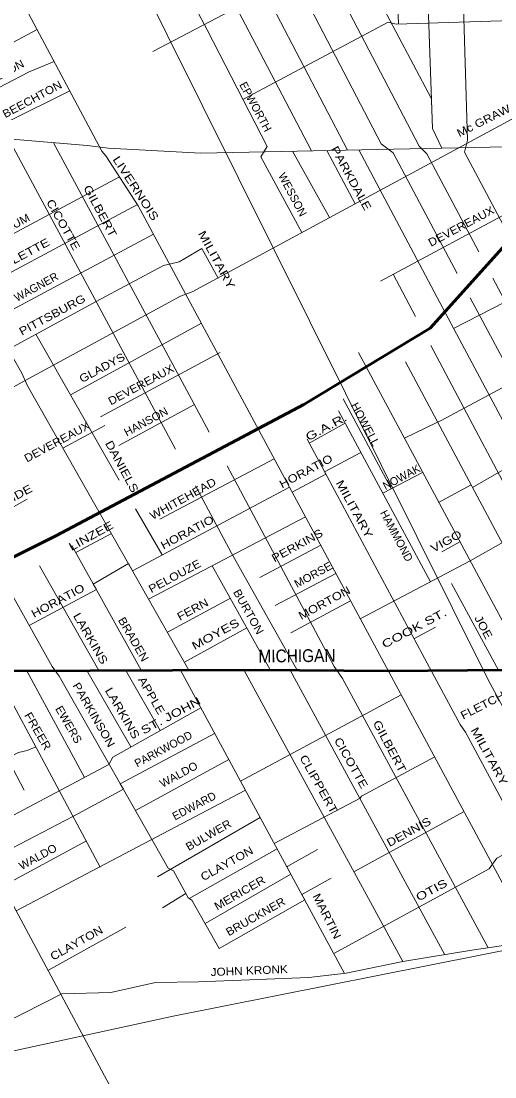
# Model space of a CAD drawing. Extents: x 34705 to 138605, y 34275 to 143551.
# Drawn here: x 76640 to 81081, y 96052 to 105948 of the extents above; entities that cross this region are included whole.
import ezdxf
from ezdxf.enums import TextEntityAlignment as Align

# ---------------------------------------------------------------- set-up
doc = ezdxf.new("R2010")
doc.units = 0
doc.header["$LTSCALE"] = 30
for name, color, linetype, lineweight in [('1', 7, 'Continuous', 13), ('11', 7, 'Continuous', 13), ('50', 7, 'Continuous', 13), ('51', 7, 'Continuous', 35)]:
    doc.layers.add(name, color=color, linetype=linetype, lineweight=lineweight)

msp = doc.modelspace()

# ---------------------------------------------------------------- linework, layer by layer
at = {"layer": '1'}
for p, q in [((79336.97, 107393.55), (80482.05, 105225.38)), ((76526.27, 104843.04), (78087.16, 101937.59)), ((79182.23, 104729.2), (79529.11, 104106.04)), ((79505.13, 104735.87), (79771.58, 104236.98)), ((76068.54, 103690.72), (77561.14, 104489.35)), ((76211.58, 103415.72), (77731.03, 104228.71)), ((80126.03, 103575.2), (80335.18, 103180.12)), ((81060.36, 103538.87), (83000.02, 99882.54)), ((80850.45, 103354.36), (82698.38, 99879.92)), ((77109.3, 102447.52), (78330.31, 103116.38)), ((76777.04, 103013.06), (77559.48, 101646.02)), ((77382.57, 102238.13), (78504.74, 102843.02)), ((79800.98, 102840.94), (81370.26, 99915.88)), ((77557, 101970.59), (78266.35, 102354.46)), ((79657.99, 102407.96), (80109.94, 101566.72)), ((79616, 102294.02), (80476.35, 100692.63)), ((77031.99, 101946.93), (77423.27, 102158.17)), ((79338.89, 101993.48), (79676.91, 102180.66)), ((77940.75, 101278.46), (79012.51, 101846.74)), ((80029.14, 101525.04), (80403.39, 101718.08)), ((76209.21, 101195.25), (76696.87, 101466.26)), ((77712.83, 101378.09), (77961.17, 100944.21)), ((77835.32, 100530.82), (79306.03, 101301.16)), ((77152.35, 100968.38), (77487.23, 101144.69)), ((78876.85, 100731.74), (79448.84, 101035.71)), ((80583.35, 100974.56), (80751.97, 101067.62)), ((77116.03, 101033.96), (77764.07, 99863.42)), ((76812.74, 100843.05), (77369.48, 99861.44)), ((78431.72, 100843.21), (78975.04, 99867.47)), ((79022.21, 100470.01), (79590.66, 100772.1)), ((80674.92, 100677.06), (81112.95, 99866.12)), ((78011.62, 100220.05), (78601.54, 100538.25)), ((79167.57, 100214.1), (79728.73, 100515.46)), ((78171.38, 99938.43), (78755.54, 100261.68)), ((80321.8, 100159.5), (80523.75, 100266.45)), ((76071.35, 99854.81), (76669.03, 98740.45)), ((76396.59, 99856.53), (77379.96, 98019.42)), ((76694.56, 99858.06), (77233.73, 98858.95)), ((77256.9, 99860.87), (77668.04, 99145.08)), ((77621.85, 99862.7), (77942.25, 99297.68)), ((78132.62, 99865.26), (79672.4, 97020.45)), ((78726.52, 99868.24), (80217.17, 97133.68)), ((79160.73, 99865.74), (80611.16, 97197.59)), ((77711.03, 98550.74), (78586.45, 99026.8)), ((77917.19, 97927.07), (78881.18, 98482.27)), ((79759.46, 97973.34), (80791.89, 98539.31))]:
    msp.add_line(p, q, dxfattribs=at)
for points in [[(70250.71, 99424.31), (70850.19, 99436.19), (73834.03, 101054.55), (75208.58, 101797.66), (76359.25, 102405.35), (76679.04, 102579.83), (78132.62, 103370.83), (78243.09, 103411.55), (82564.58, 105745.28), (82901.81, 106065.17), (82895.99, 106059.36), (83186.71, 106338.54), (83994.9, 106937.6), (84082.11, 106978.32), (85329.53, 107917.67), (85364.44, 107987.53), (85905.64, 108383.37), (87249.9, 109402.07), (88876.39, 110091.88)], [(74914.4, 104874.31), (75879.58, 104897.58), (77259.02, 104781.25), (77456.7, 104757.99), (78323.04, 104711.46), (84801.63, 104845.23), (85092.35, 104868.5), (85377.25, 104932.47), (86652.03, 105479.2), (88419.59, 106217.85), (88564.94, 106305.1), (90681.35, 107194.97), (91332.56, 107474.15), (91408.14, 107549.76), (94615.68, 108918.91), (95226.7, 109227.44), (95367, 109272.3)], [(79859.14, 108820.93), (80363.34, 107847.51), (80396.14, 107775.33), (80494.54, 104940.6), (80582.81, 104758.12)], [(77358.07, 108575.44), (77940.09, 107470.6), (77986.16, 107360), (79362.95, 104732.93)], [(78018.92, 108640.3), (78644.99, 107452.17), (78695.67, 107332.34), (80015.68, 104799.53), (80127.19, 104714.23), (80728.47, 103583.71)], [(76970.6, 108537.4), (77000.23, 108482.2), (78382.38, 105865.65), (78946.44, 104773.28), (78887.41, 104674.86), (79272.02, 103967.21)], [(75461.99, 108389.33), (75949.8, 107475.21), (75982.05, 107419.91), (76018.91, 107313.91), (77396.45, 104728.46), (77433.31, 104686.98), (77737.38, 104216.9), (82924.91, 94574.55), (82977.39, 94535.18), (83082.34, 94397.38), (83174.18, 94325.2), (83252.9, 94239.89), (83370.97, 94092.26), (86141.27, 88934.48)], [(80617.6, 107976.22), (80684.77, 107834.38), (80697.89, 107368.49), (80770.05, 106613.88), (80802.85, 105557.42), (80822.52, 104832.34), (80796.29, 104720.79), (81159.02, 104037.5)], [(80065.18, 107695.98), (80114.07, 107598.16), (80175.74, 105920.44)], [(78998.92, 107532.54), (78998.92, 107427.55), (79025.16, 107355.37), (80369.9, 104776.56), (80442.06, 104704.38), (80929.37, 103785.78)], [(78307.64, 107421.61), (78589.7, 106866.87), (79699.68, 104739.88)], [(77875.34, 105663.86), (79724.29, 106635.16), (79776.62, 106646.79), (83722.42, 106735.63)], [(78719.21, 105213.34), (80078.96, 105937.22), (80154.55, 105919.77), (82817.89, 106003.49)], [(74897.81, 105042.82), (75285.06, 105060.43), (75947.89, 105421.03), (76789.15, 105868.28)], [(75914.7, 104894.62), (75843.24, 105019.72), (76715.38, 105473.38), (76949.06, 105568.14)], [(76478.69, 104847.06), (76506.07, 105002.27), (76506.07, 105002.27), (77095.16, 105293.93)], [(79819.31, 100347.1), (80849.35, 100888.78), (81157.51, 101063.26), (81390.09, 101179.59), (82385.53, 101727.1), (82404.38, 101691.59), (83852.83, 102468.28), (83914.13, 102353.8), (84532.72, 102680.17), (84619.93, 102761.59), (84869.95, 102889.55), (85242.07, 103052.4), (85300.21, 103052.4), (86410.74, 103506.06), (87338.12, 103914.64), (90408.69, 105206.69)], [(75375.48, 104885.43), (76647.46, 102649.52), (76701.26, 102529.92), (78212.65, 99865.66)], [(76943.88, 104807.83), (78258.96, 102365.42), (78403.08, 102095.22)], [(79805.86, 104742.08), (80593.07, 103258.6), (80744.67, 102970.46), (82397.49, 99877.3)], [(80693.61, 103067.51), (81174.96, 103314.13), (81791.27, 103639.84), (82163.39, 103843.4), (83252.36, 104429.51)], [(74488.02, 104311.75), (74944.76, 103434.72), (74944.76, 103434.72), (75692.26, 102103.72), (75746.06, 102031.92), (76499.46, 100670.92), (76930.06, 99899.22), (76995.76, 99809.52), (78019.76, 98007.42), (78067.66, 97983.52), (78205.16, 97732.22), (78241.06, 97708.32), (78496.67, 97256.25)], [(80006.99, 103511.34), (81323.96, 104217.9), (81421.52, 104314.94)], [(73058.51, 101374.39), (74455.07, 102126.17), (74495.77, 102149.43), (75135.35, 102498.41), (75199.3, 102515.85), (77208.14, 103593.31), (77879.86, 103952.05)], [(76182, 102689.76), (77341.87, 103319.95), (77975.63, 103657.29), (78120.99, 103692.18), (78335.3, 103817.24), (78487.26, 103539.66)], [(80233.04, 102040.38), (80535.38, 102185.79), (80576.08, 102203.24), (83233.6, 103624.89)], [(73374.93, 103580.67), (73766.86, 102827.52), (73832.56, 102809.62), (74574.06, 101445.62), (75417.16, 99887.32), (75423.16, 99791.62), (80033.46, 91181.82), (80063.36, 91104.02), (80087.26, 90918.52), (80105.16, 90810.92), (80827.3, 89465.66)], [(80552.82, 101435.5), (80856.97, 101602.43), (80870.05, 101577.95), (81343.57, 101848.45), (81361.01, 101865.9), (81581.96, 101988.04), (82111.06, 102273.03), (82157.57, 102302.11), (83018.09, 102767.41), (83070.42, 102685.98), (83585.74, 102967.16)], [(80478.99, 102908.46), (81488.33, 101001.86), (82072.15, 99915.88), (82065.59, 99804.33), (82555.16, 98882.12)], [(80241.21, 102755.03), (81186.58, 100985.47), (81790.29, 99872.02)], [(79319.72, 102029.25), (80445.33, 99929.01), (80753.64, 99354.85), (80806.12, 99282.67), (82682.2, 95785.2)], [(79180.73, 101534.06), (79496.02, 101700.3), (79483.57, 101723.53), (79825.65, 101903.8)], [(78571.76, 101779.01), (79574.46, 99899.22), (79652.26, 99785.62), (81016.16, 97261.28)], [(76716.6, 100281.77), (77344.93, 100620.51), (77316.69, 100671.51), (77645.52, 100865.39), (77684.19, 100797.23), (79156.76, 101578.61)], [(78273.13, 101591.43), (78611.76, 100961.12), (79228.25, 99865.11)], [(76592.7, 97607.49), (78741.86, 98740.85), (78696.68, 98823.14), (80201.27, 99632.68)], [(76212.6, 98317.34), (77463.29, 98980.71), (77498.2, 99050.56), (77498.2, 99050.56), (78324.54, 99510.43)], [(76338.12, 98082.92), (77131.59, 98497.55), (77598.24, 98749.23), (77569.43, 98799.93), (78452.57, 99271.76)], [(75004.55, 98225.68), (75963.36, 98743.49), (76027.37, 98790.06), (76615.12, 99092.76), (76696.59, 99110.23), (76776.6, 99146.6)], [(77963.75, 97636.01), (78184.7, 97769.8), (78205.16, 97732.22), (78214.92, 97725.72), (79040.3, 98189.03), (79011.85, 98240.85), (79817.2, 98666.36), (79828.83, 98683.83), (80516.54, 99051.11)], [(79570.25, 97209.17), (81027.61, 98002.75), (81097.44, 98101.71), (81685.03, 98412.88)], [(76467.36, 97841.56), (77253.79, 98264.7), (77253.79, 98264.7)], [(78364.87, 97489.36), (79168.12, 97952.7), (79131.2, 98020.33), (79139.24, 98026.03), (79418.57, 98183.21)], [(79546.6, 97915.43), (79270.57, 97762.85), (79298.93, 97710.46), (78496.67, 97256.25)], [(72840.79, 95705.51), (75339.24, 96190.9), (75740.78, 96260.76), (75996.82, 96348.08), (76287.79, 96458.68), (77021.02, 96831.23), (77480.75, 96842.88), (77899.73, 96936.01), (78301.27, 96941.84), (79337.1, 96982.58), (79686.26, 97023.33), (80218.73, 97133.93), (80864.67, 97238.72), (81138.18, 97279.46), (81475.69, 97374.06), (81801.14, 97427.72), (81747.3, 97528.08), (82063.69, 97698.28)], [(76891.36, 97049.75), (77620.41, 97455.56), (77620.41, 97455.56)]]:
    msp.add_lwpolyline(points, dxfattribs=at)
at = {"layer": '1', "lineweight": 53}
msp.add_lwpolyline([(70273.25, 98655.39), (71057.35, 98936.8), (71901.7, 99280.47), (72734.73, 99461.12), (73549.47, 99618.3), (74194.43, 99751.98), (74462.66, 99868.63), (74760.14, 99892.09), (75412.24, 99851.32), (76511.78, 99857.14), (78835.21, 99868.78), (80080.52, 99857.14), (86770.24, 99915.34), (86956.45, 99956.09), (88909.68, 99973.56), (89759.8, 99996.86), (90394.28, 99932.82), (90847.72, 99926.99), (94474.35, 99938.64), (95736.38, 99991), (96334.87, 100081.57)], dxfattribs=at)
at = {"layer": '50'}
for points in [[(81906.05, 98139.06), (81018.13, 99774.79), (76672.7, 108508.16)], [(72952.8, 95508.64), (78064.89, 96622.26), (81430.09, 97291.04), (86167.76, 98196.23), (89160.46, 98763.08), (89727.54, 98776.38), (90401.7, 98740.87), (90973.35, 98653.39), (91592.71, 98503.02), (92169.12, 98306.86)]]:
    msp.add_lwpolyline(points, dxfattribs=at)
at = {"layer": '51', "lineweight": 60}
msp.add_lwpolyline([(69855.84, 98897.31), (71068.51, 99251.13), (71798.78, 99505.57), (71908.53, 99566.11), (73894.22, 100075), (74115.76, 100095.52), (75030.66, 100259.68), (75589.64, 100438.2), (76964.04, 101123.57), (79290.25, 102354.77), (80472.84, 103069.89), (82167.24, 104949.52), (82488.27, 105229.61), (83616.5, 105873.94), (83928.31, 105972.43), (86533.5, 107068.2), (87067.87, 107328.8), (89988.97, 108477.92)], dxfattribs=at)

# ---------------------------------------------------------------- texts
at = {"layer": '11'}
for s, height, rotation, width, p in [('WALTON', 75, 28.253, 1.05, (76477.67, 105418.41)), ('BEECHTON', 75, 28.252, 1.1, (76761.09, 105182.31)), ('Mc GRAW', 75, 26.74, 1.15, (80990.94, 104981.01)), ('PARKDALE ', 75, 298.729, 1.25, (79709.19, 104442.4)), ('LIVERNOIS', 75, 302.897, 1.3, (77682.92, 104360.99)), ('GILBERT', 75, 298.252, 1.25, (77347.77, 104149.92)), ('CICOTTE', 75, 299.253, 1.2, (77002.25, 104022.12)), ('DEVEREAUX', 75, 27.998, 1.1, (80781.5, 103991.88)), ('BARLUM', 75, 28.253, 1.1, (76528.39, 103972.44)), ('WILLETTE', 75, 28.253, 1.25, (76645.66, 103707.22)), ('MILITARY', 75, 298.614, 1.3, (78439.01, 103693.66)), ('PITTSBURG', 75, 28.254, 1.2, (76949.83, 103162.21)), ('GLADYS', 75, 28.325, 1.15, (77416.03, 102666.14)), ('DEVEREAUX', 75, 28.327, 1.1, (77780.66, 102506.96)), ('HANSON', 75, 28.328, 1.05, (77827.49, 102160.74)), ('HOWELL', 75, 298.223, 1.05, (79833.57, 102151.87)), ('G.A.R.', 75, 28.221, 1.4, (79516.9, 102109.71)), ('DEVEREAUX', 75, 28.327, 1.1, (76993.87, 101971.45)), ('DANIELS', 75, 298.324, 1.25, (77551.7, 101755.43)), ('HORATIO', 75, 28.223, 1.2, (79327.11, 101696.14)), ('WHITEHEAD', 75, 28.846, 1.15, (78174.34, 101438.65)), ('MILITARY', 75, 298.614, 1.3, (79730.65, 101356.81)), ('IRONSIDE', 75, 28.329, 1.25, (76486.63, 101399.38)), ('LINZEE', 75, 28.847, 1.3, (77312.44, 101090.13)), ('HORATIO', 75, 28.223, 1.2, (78214.73, 101123.81)), ('PERKINS', 75, 28.693, 1.2, (79245.68, 101000.19)), ('VIGO', 75, 28.693, 1.25, (80641.63, 101039.98)), ('PELOUZE', 75, 28.327, 1.15, (78097.08, 100712.66)), ('MORSE', 75, 28.693, 1.05, (79395.45, 100726.47)), ('HORATIO', 75, 28.223, 1.2, (77002.17, 100482.16)), ('MORTON ', 75, 28.693, 1.2, (79514.77, 100470.08)), ('BURTON', 75, 299.355, 1.1, (78738.25, 100393.94)), ('FERN', 75, 28.333, 1.15, (78265.75, 100400.95)), ('LARKINS', 75, 300.069, 1.25, (77258.65, 100143.28)), ('BRADEN', 75, 300.069, 1.1, (77660.36, 100135.35)), ('COOK ST. ', 75, 28.034, 1.4, (80358.72, 100233.31)), ('JOE', 75, 298.223, 1.2, (80941.16, 100250.99)), ('MOYES  ', 75, 28.693, 1.35, (78512.55, 100187.12)), ('MICHIGAN', 120, 0.658, 0.9, (79226.25, 99939.54)), ('PARKINSON', 75, 300.069, 1.15, (77289.48, 99427.88)), ('APPLE', 75, 300.069, 1.2, (77829.4, 99608.52)), ('LARKINS', 75, 300.069, 1.25, (77557.07, 99443.1)), ('FLETCHER', 75, 27.195, 1.15, (81053.92, 99538.72)), ('ST. JOHN', 75, 28.214, 1.35, (78059.47, 99405.95)), ('FREER', 75, 300.068, 1.15, (76764.75, 99274.39)), ('EWERS', 75, 300.068, 1.05, (77053.73, 99336.23)), ('GILBERT', 75, 298.037, 1.25, (80060.46, 99133.77)), ('MILITARY', 75, 298.614, 1.3, (80995.53, 99039.75)), ('CICOTTE', 75, 299.355, 1.2, (79700.15, 98977.49)), ('CLIPPERT', 75, 299.358, 1.25, (79396.98, 98777.56)), ('WALDO', 75, 28.537, 1.05, (78134.58, 98853.49)), ('DENNIS', 75, 28.731, 1.2, (80291.65, 98315.79)), ('BULWER', 75, 29.939, 1.1, (78414.62, 98286.75)), ('WALDO', 75, 28.537, 1.05, (76813.83, 98082.46)), ('CLAYTON', 75, 29.307, 1.15, (78586.3, 98019.08)), ('MERICER', 75, 29.977, 1.15, (78707.39, 97744.12)), ('OTIS', 75, 28.197, 1.35, (80504.51, 97770.51)), ('MARTIN', 75, 296.688, 1.2, (79473.3, 97541.7)), ('BRUCKNER', 75, 29.525, 1.1, (78855.16, 97522.42)), ('CLAYTON', 75, 29.307, 1.15, (77177.29, 97273.96)), ('JOHN KRONK', 75, 2.252, 1.1, (78779.14, 97011.34))]:
    msp.add_text(s, height=height, rotation=rotation, dxfattribs=dict(at, width=width)).set_placement(p, align=Align.CENTER)
for s, rotation, p in [('EPWORTH', 298.223, (78803.92, 105127.79)), ('WESSON', 298.037, (79150.82, 104304.43)), ('WAGNER', 28.699, (76799.1, 103423.66)), ('NOWAK', 28.221, (80222.12, 101640.96)), ('HAMMOND', 298.223, (80125.7, 101105.93)), ('PARKWOOD', 28.213, (77990.78, 99091.98)), ('EDWARD', 27.805, (78278.88, 98559.15))]:
    msp.add_text(s, height=75, rotation=rotation, dxfattribs=at).set_placement(p, align=Align.CENTER)

doc.saveas('drawing.dxf')
